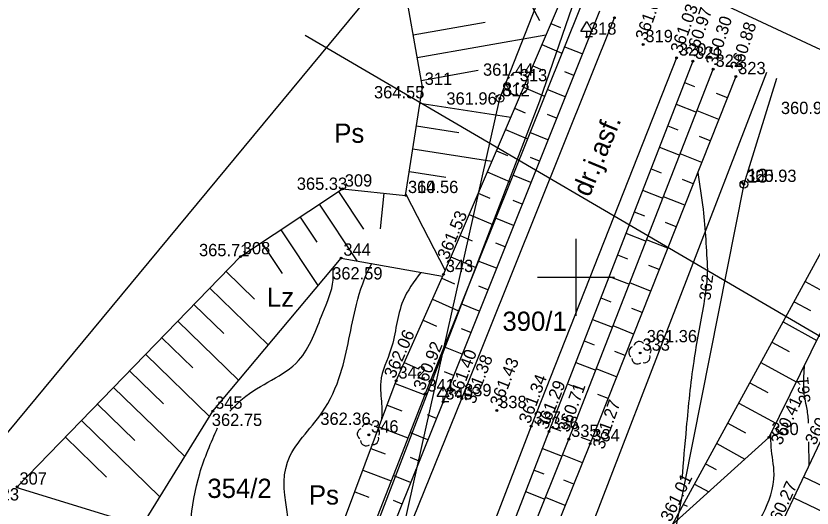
# Model space of a CAD drawing. Extents: x 4635329 to 4651863, y 5356628 to 5367582.
# Drawn here: x 4651713.6 to 4651765.3, y 5357185 to 5357217 of the extents above; entities that cross this region are included whole.
import ezdxf

# ---------------------------------------------------------------- set-up
doc = ezdxf.new("R2010")
doc.units = 0
for name, color, linetype in [('Level 1', 7, 'Continuous'), ('Level 12', 7, 'Continuous'), ('Level 2', 7, 'Continuous'), ('Level 20', 7, 'Continuous'), ('Level 21', 7, 'Continuous'), ('Level 24', 7, 'Continuous'), ('Level 4', 7, 'Continuous'), ('Level 44', 7, 'Continuous'), ('Level 45', 7, 'Continuous'), ('Level 46', 7, 'Continuous'), ('Level 47', 7, 'Continuous'), ('Level 48', 7, 'Continuous'), ('Level 5', 7, 'Continuous'), ('Level 55', 7, 'Continuous'), ('Level 60', 7, 'Continuous'), ('Level 62', 7, 'Continuous'), ('Level 63', 7, 'Continuous'), ('Level 7', 7, 'Continuous')]:
    doc.layers.add(name, color=color, linetype=linetype)

msp = doc.modelspace()

# ---------------------------------------------------------------- linework, layer by layer
at = {"layer": 'Level 1'}
for p, q in [((4651784.412, 5357206.105), (4651748.153, 5357223.087)), ((4651738.209, 5357220.297), (4651710.481, 5357186.845))]:
    msp.add_line(p, q, dxfattribs=at)
at = {"layer": 'Level 2'}
msp.add_line((4651793.081, 5357180.253), (4651732.387, 5357215.712), dxfattribs=at)
at = {"layer": 'Level 20'}
for points in [[(4651729.82, 5357135.56), (4651729.11, 5357142.98), (4651728.67, 5357151.53), (4651729.317, 5357155.805), (4651729.9, 5357158.7), (4651733.24, 5357168.87), (4651737.34, 5357179.25), (4651742.57, 5357192.12), (4651752.49, 5357216.86)], [(4651756.54, 5357214.25), (4651747.08, 5357190.33), (4651742.11, 5357177.45), (4651737.72, 5357166.81), (4651734.98, 5357158.12), (4651734.207, 5357154.352), (4651733.71, 5357151.02), (4651733.66, 5357143.55), (4651734.7, 5357135.16)], [(4651721.76, 5357183.82), (4651713.66, 5357186.32)]]:
    msp.add_lwpolyline(points, dxfattribs=at)
at = {"layer": 'Level 24'}
for p, q in [((4651750.69, 5357215.61), (4651750.69, 5357215.96)), ((4651751.065, 5357215.61), (4651750.69, 5357215.61)), ((4651741.35, 5357191.91), (4651741.35, 5357192.26)), ((4651741.725, 5357191.91), (4651741.35, 5357191.91))]:
    msp.add_line(p, q, dxfattribs=at)
for points in [[(4651751.065, 5357215.96), (4651750.315, 5357215.96), (4651750.69, 5357216.61)], [(4651741.725, 5357192.26), (4651740.975, 5357192.26), (4651741.35, 5357192.91)]]:
    msp.add_lwpolyline(points, close=True, dxfattribs=at)
at = {"layer": 'Level 4'}
for p, q in [((4651745.05, 5357211.61), (4651747.935, 5357218.966)), ((4651746.741, 5357218.343), (4651747.62, 5357216.676)), ((4651747.646, 5357211.452), (4651750.011, 5357218.306)), ((4651748.54, 5357177.401), (4651762.4, 5357213.326)), ((4651763.031, 5357212.917), (4651760.91, 5357206.04)), ((4651730.567, 5357167.111), (4651747.646, 5357211.452)), ((4651733.96, 5357162.18), (4651745.05, 5357211.61)), ((4651760.91, 5357206.04), (4651751.63, 5357159.48))]:
    msp.add_line(p, q, dxfattribs=at)
at = {"layer": 'Level 44'}
for centre in [(4651752.49, 5357216.86), (4651754.36, 5357215.12), (4651756.54, 5357214.25), (4651757.59, 5357214.04), (4651758.92, 5357213.52), (4651760.39, 5357213.04), (4651740.01, 5357212.35), (4651746.19, 5357212.58), (4651745.05, 5357211.61), (4651734.81, 5357205.74), (4651760.91, 5357206.04), (4651738.92, 5357205.32), (4651728.18, 5357201.34), (4651734.72, 5357201.25), (4651741.38, 5357200.19), (4651754.17, 5357195.08), (4651738.3, 5357193.27), (4651740.18, 5357192.43), (4651741.35, 5357191.91), (4651742.57, 5357192.12), (4651726.38, 5357191.31), (4651744.85, 5357191.35), (4651747.08, 5357190.33), (4651736.52, 5357189.76), (4651748.24, 5357189.98), (4651762.54, 5357189.6), (4651749.53, 5357189.48), (4651750.91, 5357189.19), (4651713.66, 5357186.38)]:
    msp.add_circle(centre, 0.04, dxfattribs=at)
at = {"layer": 'Level 46'}
for p, q in [((4651764.818, 5357193.467), (4651764.842, 5357194.272)), ((4651765.156, 5357187.787), (4651765.129, 5357189.304))]:
    msp.add_line(p, q, dxfattribs=at)
for points in [[(4651757.908, 5357206.797), (4651758.256, 5357204.416), (4651758.542, 5357200.481)], [(4651727.492, 5357191.297), (4651728.322, 5357192.111), (4651731.96, 5357194.598), (4651733.537, 5357197.691), (4651734.204, 5357199.814), (4651734.204, 5357200.635)], [(4651731.177, 5357180.25), (4651731.354, 5357180.769), (4651731.233, 5357187.987), (4651733.476, 5357191.202), (4651734.689, 5357193.749), (4651735.719, 5357198.237), (4651736.69, 5357200.845), (4651736.715, 5357200.891)], [(4651758.542, 5357200.481), (4651758.498, 5357199.746), (4651758.302, 5357198.272)], [(4651739.905, 5357200.317), (4651738.751, 5357198.48), (4651737.963, 5357195.326), (4651737.296, 5357193.203), (4651737.356, 5357191.747), (4651737.356, 5357190.738)], [(4651758.302, 5357198.272), (4651757.649, 5357194.529), (4651757.164, 5357190.223), (4651756.877, 5357186.9)], [(4651764.98, 5357191.641), (4651764.8, 5357192.887), (4651764.818, 5357193.467)], [(4651765.108, 5357190.516), (4651765.104, 5357190.764), (4651764.98, 5357191.641)], [(4651724.748, 5357180.582), (4651725.533, 5357187.259), (4651726.691, 5357190.229)], [(4651756.02, 5357173.414), (4651756.322, 5357175.932), (4651760.142, 5357181.815), (4651762.143, 5357184.605), (4651762.871, 5357187.213), (4651762.689, 5357188.972), (4651762.659, 5357189.841)]]:
    msp.add_spline(points, degree=3, dxfattribs=at)
at = {"layer": 'Level 48'}
for p, q in [((4651739.409, 5357215.747), (4651744.079, 5357216.573)), ((4651748.361, 5357216.492), (4651748.995, 5357216.221)), ((4651739.67, 5357214.27), (4651748.044, 5357215.751)), ((4651747.771, 5357215.113), (4651749.07, 5357214.557)), ((4651750.404, 5357214.505), (4651749.237, 5357214.973)), ((4651739.932, 5357212.793), (4651743.635, 5357213.448)), ((4651747.18, 5357213.734), (4651747.845, 5357213.45)), ((4651749.846, 5357213.113), (4651749.262, 5357213.347)), ((4651746.59, 5357212.356), (4651747.951, 5357211.773)), ((4651757.047, 5357212.642), (4651757.711, 5357212.384)), ((4651749.288, 5357211.721), (4651748.118, 5357212.189)), ((4651759.836, 5357211.646), (4651759.123, 5357211.93)), ((4651739.849, 5357211.312), (4651745.751, 5357210.397)), ((4651745.999, 5357210.977), (4651746.696, 5357210.679)), ((4651756.503, 5357211.244), (4651757.83, 5357210.728)), ((4651759.282, 5357210.252), (4651757.864, 5357210.816)), ((4651748.73, 5357210.328), (4651748.145, 5357210.563)), ((4651739.619, 5357209.83), (4651742.38, 5357209.402)), ((4651755.96, 5357209.846), (4651756.622, 5357209.588)), ((4651745.409, 5357209.598), (4651746.832, 5357208.988)), ((4651748.172, 5357208.936), (4651747, 5357209.406)), ((4651758.728, 5357208.858), (4651758.023, 5357209.138)), ((4651739.389, 5357208.347), (4651744.532, 5357207.55)), ((4651744.818, 5357208.219), (4651745.546, 5357207.907)), ((4651755.417, 5357208.447), (4651756.738, 5357207.934)), ((4651747.614, 5357207.543), (4651747.028, 5357207.779)), ((4651758.174, 5357207.464), (4651756.772, 5357208.021)), ((4651739.16, 5357206.865), (4651741.541, 5357206.496)), ((4651744.228, 5357206.84), (4651745.714, 5357206.204)), ((4651754.873, 5357207.049), (4651755.533, 5357206.793)), ((4651747.057, 5357206.151), (4651745.882, 5357206.622)), ((4651757.62, 5357206.07), (4651756.923, 5357206.347)), ((4651754.33, 5357205.651), (4651755.647, 5357205.14)), ((4651734.556, 5357205.571), (4651736.173, 5357203.134)), ((4651737.491, 5357205.466), (4651737.254, 5357203.151)), ((4651738.931, 5357205.389), (4651741.483, 5357200.431)), ((4651743.637, 5357205.461), (4651744.396, 5357205.136)), ((4651757.066, 5357204.676), (4651755.681, 5357205.227)), ((4651733.306, 5357204.742), (4651735.746, 5357201.065)), ((4651746.499, 5357204.759), (4651745.91, 5357204.994)), ((4651743.047, 5357204.082), (4651744.595, 5357203.419)), ((4651753.787, 5357204.253), (4651754.444, 5357203.998)), ((4651732.056, 5357203.912), (4651733.138, 5357202.283)), ((4651745.941, 5357203.366), (4651744.763, 5357203.838)), ((4651756.512, 5357203.283), (4651755.823, 5357203.556)), ((4651730.806, 5357203.083), (4651733.214, 5357199.455)), ((4651742.456, 5357202.703), (4651743.246, 5357202.365)), ((4651753.243, 5357202.855), (4651754.555, 5357202.345)), ((4651729.557, 5357202.254), (4651730.883, 5357200.255)), ((4651745.383, 5357201.974), (4651744.793, 5357202.21)), ((4651755.958, 5357201.889), (4651754.589, 5357202.433)), ((4651741.866, 5357201.325), (4651743.476, 5357200.635)), ((4651744.825, 5357200.582), (4651743.645, 5357201.054)), ((4651752.7, 5357201.457), (4651753.355, 5357201.202)), ((4651755.403, 5357200.495), (4651754.723, 5357200.765)), ((4651727.241, 5357200.373), (4651729.099, 5357198.569)), ((4651741.272, 5357199.947), (4651742.09, 5357199.583)), ((4651752.157, 5357200.059), (4651753.464, 5357199.551)), ((4651744.267, 5357199.189), (4651743.676, 5357199.426)), ((4651754.849, 5357199.101), (4651753.498, 5357199.638)), ((4651764.892, 5357199.73), (4651766.973, 5357198.595)), ((4651726.197, 5357199.296), (4651729.991, 5357195.614)), ((4651740.662, 5357198.577), (4651742.348, 5357197.826)), ((4651751.613, 5357198.66), (4651752.266, 5357198.407)), ((4651764.174, 5357198.414), (4651765.241, 5357197.831)), ((4651725.152, 5357198.22), (4651727.088, 5357196.341)), ((4651743.709, 5357197.797), (4651742.526, 5357198.271)), ((4651754.295, 5357197.707), (4651753.624, 5357197.974)), ((4651724.107, 5357197.144), (4651728.058, 5357193.309)), ((4651740.052, 5357197.206), (4651740.92, 5357196.82)), ((4651751.07, 5357197.262), (4651752.372, 5357196.756)), ((4651753.741, 5357196.313), (4651752.406, 5357196.844)), ((4651763.455, 5357197.097), (4651765.645, 5357195.902)), ((4651743.151, 5357196.404), (4651742.559, 5357196.642)), ((4651723.062, 5357196.067), (4651725.077, 5357194.112)), ((4651750.527, 5357195.864), (4651751.177, 5357195.612)), ((4651742.593, 5357195.012), (4651741.408, 5357195.487)), ((4651762.737, 5357195.78), (4651763.859, 5357195.168)), ((4651722.018, 5357194.991), (4651726.167, 5357190.964)), ((4651753.187, 5357194.919), (4651752.524, 5357195.183)), ((4651738.832, 5357194.466), (4651739.751, 5357194.057)), ((4651749.983, 5357194.466), (4651751.281, 5357193.962)), ((4651762.018, 5357194.464), (4651764.318, 5357193.209)), ((4651720.973, 5357193.915), (4651723.167, 5357191.786)), ((4651742.035, 5357193.62), (4651741.442, 5357193.857)), ((4651752.633, 5357193.525), (4651751.315, 5357194.049)), ((4651719.928, 5357192.838), (4651724.554, 5357188.349)), ((4651738.233, 5357193.091), (4651740.158, 5357192.373)), ((4651749.44, 5357193.068), (4651750.088, 5357192.816)), ((4651761.3, 5357193.147), (4651762.477, 5357192.504)), ((4651752.079, 5357192.131), (4651751.424, 5357192.392)), ((4651718.884, 5357191.762), (4651721.315, 5357189.402)), ((4651737.709, 5357191.685), (4651738.661, 5357191.33)), ((4651760.581, 5357191.83), (4651762.991, 5357190.515)), ((4651717.839, 5357190.685), (4651722.941, 5357185.734)), ((4651740.918, 5357190.835), (4651740.331, 5357191.071)), ((4651737.185, 5357190.28), (4651739.07, 5357189.577)), ((4651748.353, 5357190.272), (4651748.999, 5357190.021)), ((4651759.863, 5357190.514), (4651761.013, 5357189.886)), ((4651716.794, 5357189.609), (4651719.464, 5357187.018)), ((4651740.36, 5357189.443), (4651739.199, 5357189.909)), ((4651750.971, 5357189.343), (4651750.324, 5357189.6)), ((4651759.144, 5357189.197), (4651760.984, 5357188.193)), ((4651736.661, 5357188.874), (4651737.593, 5357188.527)), ((4651747.81, 5357188.874), (4651749.087, 5357188.377)), ((4651739.801, 5357188.051), (4651739.228, 5357188.281)), ((4651750.411, 5357187.952), (4651749.124, 5357188.47)), ((4651758.426, 5357187.88), (4651759.116, 5357187.504)), ((4651736.137, 5357187.469), (4651737.981, 5357186.781)), ((4651739.242, 5357186.659), (4651738.11, 5357187.113)), ((4651747.266, 5357187.476), (4651747.897, 5357187.23)), ((4651764.795, 5357187.027), (4651769.912, 5357184.596)), ((4651749.85, 5357186.561), (4651749.207, 5357186.82)), ((4651757.707, 5357186.563), (4651758.627, 5357186.061)), ((4651735.613, 5357186.063), (4651736.525, 5357185.723)), ((4651746.722, 5357186.078), (4651747.968, 5357185.593)), ((4651738.683, 5357185.267), (4651738.125, 5357185.491)), ((4651749.289, 5357185.169), (4651748.005, 5357185.687)), ((4651764.152, 5357185.672), (4651766.74, 5357184.442)), ((4651756.989, 5357185.247), (4651757.219, 5357185.121))]:
    msp.add_line(p, q, dxfattribs=at)
for points in [[(4651713.66, 5357186.38), (4651728.18, 5357201.34), (4651734.81, 5357205.74), (4651738.92, 5357205.32), (4651740.01, 5357212.35), (4651738.644, 5357220.072)], [(4651731.56, 5357173.2), (4651733.61, 5357180.69), (4651738.3, 5357193.27), (4651741.38, 5357200.19), (4651749.11, 5357218.24)], [(4651750.3, 5357217.62), (4651740.18, 5357192.43), (4651735.38, 5357180.1), (4651732.665, 5357172.888)], [(4651751.52, 5357217.29), (4651741.35, 5357191.91), (4651736.4, 5357179.58), (4651733.75, 5357172.51)], [(4651757.59, 5357214.04), (4651748.24, 5357189.98), (4651743.2, 5357177.02), (4651738.89, 5357166.25), (4651736.04, 5357158.01)], [(4651737.04, 5357157.53), (4651740.4, 5357165.7), (4651744.32, 5357176.52), (4651749.53, 5357189.48), (4651758.92, 5357213.52)], [(4651760.39, 5357213.04), (4651750.91, 5357189.19), (4651745.61, 5357176.04), (4651741.85, 5357165.37), (4651738.55, 5357157.51)], [(4651756.27, 5357183.93), (4651769.94, 5357208.98)], [(4651771.4, 5357207.58), (4651762.54, 5357189.6), (4651756.27, 5357183.93)], [(4651742.61, 5357155.07), (4651748.7, 5357162.32), (4651754.89, 5357171.81), (4651763.11, 5357183.48), (4651765.69, 5357188.91), (4651773.53, 5357204.88)], [(4651721.76, 5357183.82), (4651726.38, 5357191.31), (4651734.72, 5357201.25), (4651741.322, 5357200.062)]]:
    msp.add_lwpolyline(points, dxfattribs=at)
at = {"layer": 'Level 55'}
for centre in [(4651746.187, 5357212.573), (4651754.17, 5357195.08), (4651736.52, 5357189.76)]:
    msp.add_circle(centre, 0.045, dxfattribs=at)
for centre, start, end in [((4651745.815, 5357212.623), 112.4389, 232.0902), ((4651746.12, 5357212.942), 40.3488, 160.1306), ((4651746.517, 5357212.75), 328.348, 88.132), ((4651746.458, 5357212.313), 256.3906, 16.0419), ((4651746.024, 5357212.235), 184.3875, 304.0933), ((4651754.103, 5357195.449), 40.3488, 160.1306), ((4651753.799, 5357195.13), 112.4389, 232.0902), ((4651754.5, 5357195.258), 328.348, 88.132), ((4651754.441, 5357194.821), 256.3906, 16.0419), ((4651754.007, 5357194.742), 184.3875, 304.0933), ((4651736.149, 5357189.81), 112.4389, 232.0902), ((4651736.453, 5357190.129), 40.3488, 160.1306), ((4651736.85, 5357189.938), 328.348, 88.132), ((4651736.791, 5357189.501), 256.3906, 16.0419), ((4651736.357, 5357189.422), 184.3875, 304.0933)]:
    msp.add_arc(centre, 0.375, start, end, dxfattribs=at)
at = {"layer": 'Level 60'}
for p, q in [((4651750, 5357197.5), (4651750, 5357202.5)), ((4651747.5, 5357200), (4651752.5, 5357200))]:
    msp.add_line(p, q, dxfattribs=at)
at = {"layer": 'Level 62'}
for centre in [(4651744.84, 5357211.76), (4651760.78, 5357206.15)]:
    msp.add_circle(centre, 0.05, dxfattribs=at)
at = {"layer": 'Level 63'}
for centre in [(4651752.49, 5357216.86), (4651750.69, 5357215.61), (4651754.36, 5357215.12), (4651756.54, 5357214.25), (4651757.59, 5357214.04), (4651758.92, 5357213.52), (4651760.39, 5357213.04), (4651740.01, 5357212.35), (4651746.19, 5357212.58), (4651745.05, 5357211.61), (4651734.81, 5357205.74), (4651760.91, 5357206.04), (4651738.92, 5357205.32), (4651728.18, 5357201.34), (4651734.72, 5357201.25), (4651741.38, 5357200.19), (4651754.17, 5357195.08), (4651738.3, 5357193.27), (4651740.18, 5357192.43), (4651742.57, 5357192.12), (4651741.35, 5357191.91), (4651726.38, 5357191.31), (4651744.85, 5357191.35), (4651747.08, 5357190.33), (4651736.52, 5357189.76), (4651748.24, 5357189.98), (4651762.54, 5357189.6), (4651749.53, 5357189.48), (4651750.91, 5357189.19), (4651713.66, 5357186.38)]:
    msp.add_circle(centre, 0.06, dxfattribs=at)
at = {"layer": 'Level 7'}
for centre in [(4651745.054, 5357211.617), (4651760.91, 5357206.04)]:
    msp.add_circle(centre, 0.25, dxfattribs=at)

# ---------------------------------------------------------------- texts
at = {"layer": 'Level 12'}
for s, p in [('Ps', (4651734.28, 5357208.736)), ('Lz', (4651729.898, 5357198.08)), ('Ps', (4651732.631, 5357185.236))]:
    msp.add_text(s, height=1.25, dxfattribs=at).set_placement(p)
at = {"layer": 'Level 21'}
msp.add_text('dr.j.asf. ', height=1.25, rotation=67.5793, dxfattribs=at).set_placement((4651750.872, 5357205.158))
at = {"layer": 'Level 45'}
for s, rotation, p in [('361.05', 70.4198, (4651754.573, 5357215.333)), ('361.03', 70.4275, (4651756.85, 5357214.491)), ('360.97', 71.5715, (4651757.828, 5357214.262)), ('360.30', 72.0802, (4651759.157, 5357213.695)), ('360.88', 71.9955, (4651760.725, 5357213.313)), ('361.53', 67.2135, (4651741.673, 5357201.088)), ('362.06', 66.1307, (4651738.202, 5357193.372)), ('360.92', 67.9231, (4651740.114, 5357192.586)), ('361.40', 69.6311, (4651742.427, 5357192.06)), ('361.38', 68.6741, (4651743.413, 5357191.721)), ('361.43', 68.4523, (4651745.099, 5357191.539)), ('361.34', 69.6299, (4651746.987, 5357190.438)), ('361.29', 68.4311, (4651748.133, 5357190.055)), ('360.71', 70.0995, (4651749.517, 5357189.876)), ('361.27', 70.1214, (4651751.795, 5357188.775)), ('360.41', 64.9042, (4651763.339, 5357189.041)), ('360.21', 62.4904, (4651765.542, 5357189.039)), ('361.01', 63.9684, (4651756.15, 5357184.057)), ('360.27', 65.0784, (4651763.027, 5357183.534))]:
    msp.add_text(s, height=0.8, rotation=rotation, dxfattribs=at).set_placement(p)
for s, p in [('361.44', (4651743.949, 5357213.093)), ('364.55', (4651736.862, 5357211.622)), ('361.96', (4651741.569, 5357211.215)), ('360.98', (4651763.319, 5357210.603)), ('360.93', (4651761.06, 5357206.19)), ('365.33', (4651731.843, 5357205.678)), ('364.56', (4651739.07, 5357205.47)), ('365.71', (4651725.485, 5357201.369)), ('362.59', (4651734.143, 5357199.856)), ('361.36', (4651754.593, 5357195.775)), ('362.75', (4651726.318, 5357190.339)), ('362.36', (4651733.373, 5357190.409)), ('365.23', (4651710.511, 5357185.5))]:
    msp.add_text(s, height=0.8, dxfattribs=at).set_placement(p)
at = {"layer": 'Level 47'}
for s, rotation, p in [('362', 83.4965, (4651758.736, 5357198.48)), ('361', 95.5847, (4651765.255, 5357191.88))]:
    msp.add_text(s, height=0.75, rotation=rotation, dxfattribs=at).set_placement(p)
at = {"layer": 'Level 5'}
for s, p in [('390/1', (4651745.212, 5357196.518)), ('354/2', (4651726.026, 5357185.664))]:
    msp.add_text(s, height=1.25, dxfattribs=at).set_placement(p)
at = {"layer": 'Level 62'}
for s, p in [(' 8', (4651744.84, 5357211.76)), (' 13', (4651760.78, 5357206.15))]:
    msp.add_text(s, height=0.9, dxfattribs=at).set_placement(p)
at = {"layer": 'Level 63'}
for s, p in [('318', (4651750.84, 5357215.76)), ('319', (4651754.51, 5357215.27)), ('320', (4651756.69, 5357214.4)), ('321', (4651757.74, 5357214.19)), ('322', (4651759.07, 5357213.67)), ('323', (4651760.54, 5357213.19)), ('313', (4651746.34, 5357212.73)), ('311', (4651740.16, 5357212.5)), ('312', (4651745.2, 5357211.76)), ('309', (4651734.96, 5357205.89)), ('325', (4651761.06, 5357206.19)), ('310', (4651739.07, 5357205.47)), ('308', (4651728.33, 5357201.49)), ('344', (4651734.87, 5357201.4)), ('343', (4651741.53, 5357200.34)), ('333', (4651754.32, 5357195.23)), ('342', (4651738.45, 5357193.42)), ('341', (4651740.33, 5357192.58)), ('340', (4651741.5, 5357192.06)), ('339', (4651742.72, 5357192.27)), ('345', (4651726.53, 5357191.46)), ('338', (4651745, 5357191.5)), ('337', (4651747.23, 5357190.48)), ('346', (4651736.67, 5357189.91)), ('336', (4651748.39, 5357190.13)), ('335', (4651749.68, 5357189.63)), ('334', (4651751.06, 5357189.34)), ('330', (4651762.69, 5357189.75)), ('307', (4651713.81, 5357186.53))]:
    msp.add_text(s, height=0.8, dxfattribs=at).set_placement(p)

doc.saveas('drawing.dxf')
